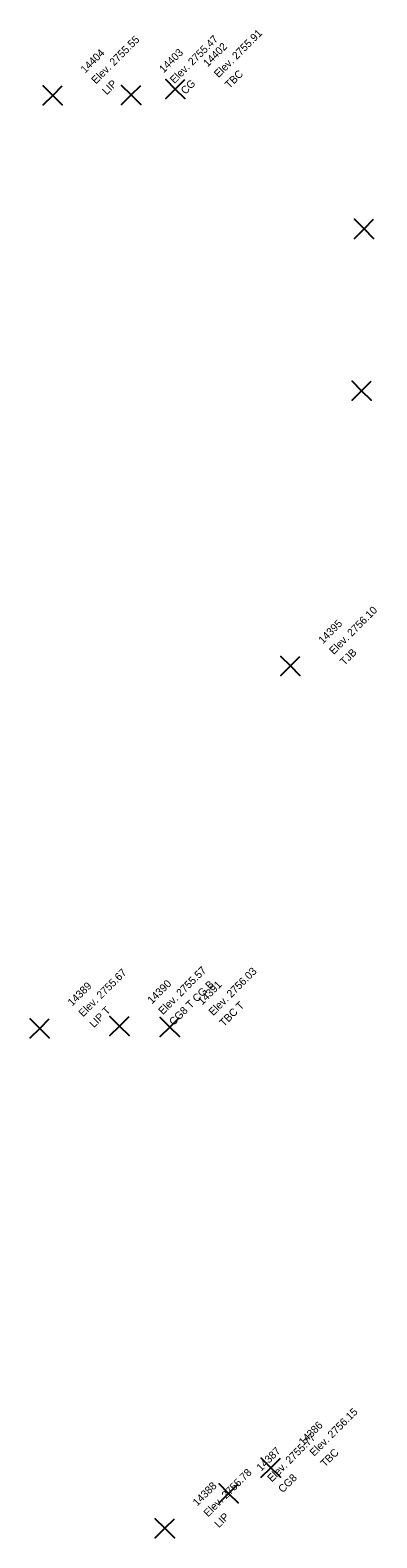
# Model space of a CAD drawing. Extents: x 2493999 to 2503109, y 700767 to 706646.
# Drawn here: x 2502319.79 to 2502325.23, y 703219.66 to 703243.32 of the extents above; entities that cross this region are included whole.
import ezdxf

# ---------------------------------------------------------------- set-up
doc = ezdxf.new("R2010")
doc.units = 0
doc.layers.add('ALG_CL_BLUE_Horiz', color=7, linetype='Continuous')
doc.layers.add('DES_SURFACE_Existing-Ground', color=7, linetype='Continuous')

msp = doc.modelspace()

# ---------------------------------------------------------------- linework, layer by layer
at = {"layer": 'ALG_CL_BLUE_Horiz'}
for points in [[(2502320.141, 703242.3), (2502319.991, 703242.45), (2502320.141, 703242.3), (2502319.991, 703242.15), (2502320.141, 703242.3), (2502320.291, 703242.15), (2502320.141, 703242.3), (2502320.291, 703242.45)], [(2502321.373, 703242.306), (2502321.223, 703242.456), (2502321.373, 703242.306), (2502321.223, 703242.156), (2502321.373, 703242.306), (2502321.523, 703242.156), (2502321.373, 703242.306), (2502321.523, 703242.456)], [(2502322.064, 703242.399), (2502321.914, 703242.549), (2502322.064, 703242.399), (2502321.914, 703242.249), (2502322.064, 703242.399), (2502322.214, 703242.249), (2502322.064, 703242.399), (2502322.214, 703242.549)], [(2502325.025, 703240.205), (2502324.875, 703240.355), (2502325.025, 703240.205), (2502324.875, 703240.055), (2502325.025, 703240.205), (2502325.175, 703240.055), (2502325.025, 703240.205), (2502325.175, 703240.355)], [(2502324.987, 703237.664), (2502324.837, 703237.814), (2502324.987, 703237.664), (2502324.837, 703237.514), (2502324.987, 703237.664), (2502325.137, 703237.514), (2502324.987, 703237.664), (2502325.137, 703237.814)], [(2502323.87, 703233.345), (2502323.72, 703233.495), (2502323.87, 703233.345), (2502323.72, 703233.195), (2502323.87, 703233.345), (2502324.02, 703233.195), (2502323.87, 703233.345), (2502324.02, 703233.495)], [(2502319.938, 703227.658), (2502319.788, 703227.808), (2502319.938, 703227.658), (2502319.788, 703227.508), (2502319.938, 703227.658), (2502320.088, 703227.508), (2502319.938, 703227.658), (2502320.088, 703227.808)], [(2502321.189, 703227.693), (2502321.039, 703227.843), (2502321.189, 703227.693), (2502321.039, 703227.543), (2502321.189, 703227.693), (2502321.339, 703227.543), (2502321.189, 703227.693), (2502321.339, 703227.843)], [(2502321.979, 703227.678), (2502321.829, 703227.828), (2502321.979, 703227.678), (2502321.829, 703227.528), (2502321.979, 703227.678), (2502322.129, 703227.528), (2502321.979, 703227.678), (2502322.129, 703227.828)], [(2502323.563, 703220.763), (2502323.413, 703220.913), (2502323.563, 703220.763), (2502323.413, 703220.613), (2502323.563, 703220.763), (2502323.713, 703220.613), (2502323.563, 703220.763), (2502323.713, 703220.913)], [(2502322.901, 703220.36), (2502322.751, 703220.51), (2502322.901, 703220.36), (2502322.751, 703220.21), (2502322.901, 703220.36), (2502323.051, 703220.21), (2502322.901, 703220.36), (2502323.051, 703220.51)], [(2502321.9, 703219.812), (2502321.75, 703219.962), (2502321.9, 703219.812), (2502321.75, 703219.662), (2502321.9, 703219.812), (2502322.05, 703219.662), (2502321.9, 703219.812), (2502322.05, 703219.962)]]:
    msp.add_lwpolyline(points, dxfattribs=at)

# ---------------------------------------------------------------- texts
at = {"layer": 'DES_SURFACE_Existing-Ground'}
for s, p in [('Elev. 2755.91', (2502322.743, 703242.569)), ('14404', (2502320.65, 703242.639)), ('Elev. 2755.55', (2502320.82, 703242.47)), ('14403', (2502321.882, 703242.645)), ('Elev. 2755.47', (2502322.052, 703242.476)), ('14402', (2502322.573, 703242.738)), ('TBC', (2502322.913, 703242.399)), ('LIP', (2502320.99, 703242.3)), ('CG', (2502322.222, 703242.306)), ('Elev. 2756.10', (2502324.549, 703233.515)), ('14395', (2502324.379, 703233.684)), ('TJB', (2502324.719, 703233.345)), ('Elev. 2755.67', (2502320.617, 703227.828)), ('Elev. 2755.57', (2502321.868, 703227.863)), ('Elev. 2756.03', (2502322.658, 703227.848)), ('14389', (2502320.447, 703227.997)), ('14390', (2502321.698, 703228.032)), ('CG8 T CG B', (2502322.038, 703227.693)), ('14391', (2502322.488, 703228.017)), ('LIP T', (2502320.787, 703227.658)), ('TBC T', (2502322.828, 703227.678)), ('Elev. 2756.15', (2502324.242, 703220.933)), ('Elev. 2755.77', (2502323.58, 703220.53)), ('14386', (2502324.072, 703221.102)), ('14387', (2502323.41, 703220.699)), ('TBC', (2502324.412, 703220.763)), ('Elev. 2755.78', (2502322.579, 703219.982)), ('CG8', (2502323.75, 703220.36)), ('14388', (2502322.409, 703220.151)), ('LIP', (2502322.749, 703219.812))]:
    msp.add_text(s, height=0.12, rotation=45, dxfattribs=at).set_placement(p)

doc.saveas('drawing.dxf')
